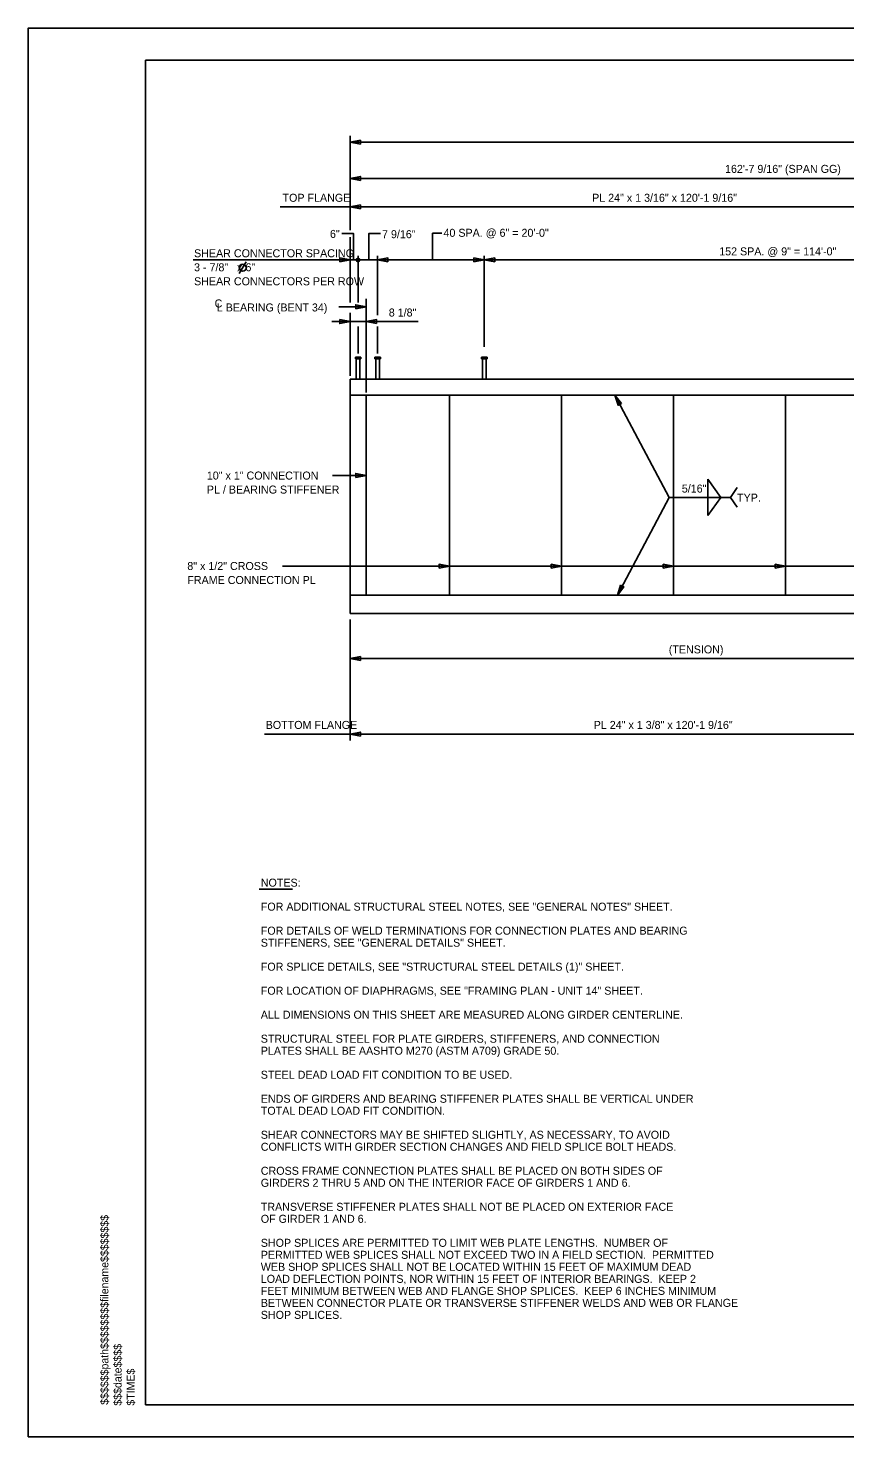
# Model space of a CAD drawing. Extents: x -305 to -161, y -187 to -99.
# Drawn here: x -305.2 to -254.1, y -187.5 to -99.5 of the extents above; entities that cross this region are included whole.
import ezdxf

# ---------------------------------------------------------------- set-up
doc = ezdxf.new("R2010")
doc.units = 0
for name, color, linetype in [('BR_AUTO DIMENSION', 7, 'Continuous'), ('BR_BORDER LINES', 7, 'Continuous'), ('BR_CENTER LINES', 7, 'Continuous'), ('BR_STRUCTURAL STEEL', 7, 'Continuous'), ('BR_TEXT', 7, 'Continuous'), ('Default', 7, 'Continuous'), ('Level 31', 7, 'Continuous'), ('RD_SHT_ID', 7, 'Continuous')]:
    doc.layers.add(name, color=color, linetype=linetype)

msp = doc.modelspace()

# ---------------------------------------------------------------- linework, layer by layer
at = {"layer": 'BR_AUTO DIMENSION'}
for p, q in [((-285.058, -112.102), (-285.058, -106.206)), ((-285.058, -106.618), (-176.638, -106.618)), ((-285.058, -108.876), (-230.848, -108.876)), ((-285.058, -110.653), (-289.428, -110.653)), ((-245.014, -110.653), (-285.055, -110.653)), ((-285.058, -116.618), (-285.058, -112.544)), ((-279.913, -113.971), (-279.913, -112.302)), ((-279.913, -112.302), (-279.327, -112.302)), ((-285.058, -113.971), (-294.871, -113.971)), ((-283.058, -113.971), (-285.058, -113.971)), ((-284.558, -116.618), (-284.558, -113.71)), ((-283.338, -117.422), (-283.338, -113.71)), ((-279.742, -113.971), (-283.055, -113.971)), ((-178.638, -113.971), (-279.742, -113.971)), ((-276.671, -119.402), (-276.671, -113.71)), ((-284.055, -116.897), (-285.757, -116.897)), ((-286.192, -117.821), (-280.799, -117.821)), ((-285.058, -121.218), (-285.058, -117.264)), ((-284.558, -119.81), (-284.558, -118.131)), ((-283.338, -119.81), (-283.338, -118.131)), ((-265.114, -128.801), (-268.502, -122.412)), ((-284.055, -127.431), (-286.165, -127.431)), ((-262.698, -127.667), (-262.698, -129.935)), ((-262.698, -127.667), (-261.892, -128.801)), ((-261.289, -128.801), (-260.856, -128.194)), ((-265.114, -128.801), (-268.355, -134.912)), ((-265.114, -128.801), (-261.289, -128.801)), ((-262.698, -129.935), (-261.892, -128.801)), ((-261.289, -128.801), (-260.856, -129.408)), ((-182.854, -133.101), (-289.275, -133.101)), ((-285.058, -136.437), (-285.058, -143.986)), ((-241.848, -138.867), (-285.058, -138.867)), ((-285.055, -143.585), (-290.402, -143.585)), ((-285.055, -143.585), (-245.014, -143.585)), ((-290.729, -153.28), (-288.653, -153.28))]:
    msp.add_line(p, q, dxfattribs=at)
for points in [[(-284.408, -106.743), (-285.058, -106.618), (-284.408, -106.493)], [(-284.408, -109.001), (-285.058, -108.876), (-284.408, -108.751)], [(-284.408, -110.778), (-285.058, -110.653), (-284.408, -110.528)], [(-285.708, -114.096), (-285.058, -113.971), (-285.708, -113.846)], [(-282.688, -114.096), (-283.338, -113.971), (-282.688, -113.846)], [(-277.321, -114.096), (-276.671, -113.971), (-277.321, -113.846)], [(-276.021, -114.096), (-276.671, -113.971), (-276.021, -113.846)], [(-284.705, -117.022), (-284.055, -116.897), (-284.705, -116.772)], [(-285.708, -117.696), (-285.058, -117.821), (-285.708, -117.946)], [(-283.405, -117.946), (-284.055, -117.821), (-283.405, -117.696)], [(-268.087, -122.928), (-268.502, -122.412), (-268.308, -123.045)], [(-284.705, -127.556), (-284.055, -127.431), (-284.705, -127.306)], [(-279.49, -133.226), (-278.84, -133.101), (-279.49, -132.976)], [(-272.49, -133.226), (-271.84, -133.101), (-272.49, -132.976)], [(-265.49, -133.226), (-264.84, -133.101), (-265.49, -132.976)], [(-258.49, -133.226), (-257.84, -133.101), (-258.49, -132.976)], [(-268.161, -134.28), (-268.355, -134.912), (-267.94, -134.397)], [(-284.408, -138.992), (-285.058, -138.867), (-284.408, -138.742)], [(-284.408, -143.71), (-285.058, -143.585), (-284.408, -143.46)]]:
    msp.add_lwpolyline(points, close=True, dxfattribs=at)
for points in [[(-284.843, -113.971), (-284.843, -112.325), (-285.583, -112.325)], [(-283.895, -113.971), (-283.895, -112.325), (-283.155, -112.325)]]:
    msp.add_lwpolyline(points, dxfattribs=at)
msp.add_circle((-284.558, -113.971), 0.111, dxfattribs=at)
at = {"layer": 'BR_BORDER LINES'}
for p, q in [((-163.178, -101.489), (-297.843, -101.489)), ((-297.843, -185.489), (-297.843, -101.489)), ((-297.843, -185.489), (-163.178, -185.489))]:
    msp.add_line(p, q, dxfattribs=at)
at = {"layer": 'BR_CENTER LINES'}
msp.add_line((-284.055, -116.402), (-284.055, -122.256), dxfattribs=at)
at = {"layer": 'BR_STRUCTURAL STEEL'}
for p, q in [((-285.058, -121.423), (-245.014, -121.423)), ((-285.058, -121.423), (-285.058, -122.412)), ((-285.058, -122.412), (-176.638, -122.412)), ((-285.058, -122.412), (-285.058, -134.912)), ((-284.055, -122.412), (-284.055, -134.912)), ((-278.84, -122.412), (-278.84, -134.912)), ((-271.84, -122.412), (-271.84, -134.912)), ((-264.84, -122.412), (-264.84, -134.912)), ((-257.84, -122.412), (-257.84, -134.912)), ((-285.058, -134.912), (-176.638, -134.912)), ((-285.058, -134.912), (-285.058, -136.058)), ((-285.058, -136.058), (-245.014, -136.058))]:
    msp.add_line(p, q, dxfattribs=at)
at = {"layer": 'BR_TEXT'}
msp.add_line((-291.979, -114.817), (-291.559, -114.089), dxfattribs=at)
msp.add_circle((-291.769, -114.453), 0.22, dxfattribs=at)
at = {"layer": 'Default'}
for p, q in [((-284.729, -120.048), (-284.729, -120.142)), ((-284.729, -120.048), (-284.386, -120.048)), ((-284.729, -120.142), (-284.386, -120.142)), ((-284.667, -120.142), (-284.667, -121.423)), ((-284.448, -120.142), (-284.448, -121.423)), ((-284.386, -120.048), (-284.386, -120.142)), ((-283.509, -120.048), (-283.509, -120.142)), ((-283.509, -120.048), (-283.166, -120.048)), ((-283.509, -120.142), (-283.166, -120.142)), ((-283.447, -120.142), (-283.447, -121.423)), ((-283.228, -120.142), (-283.228, -121.423)), ((-283.166, -120.048), (-283.166, -120.142)), ((-276.843, -120.048), (-276.843, -120.142)), ((-276.843, -120.048), (-276.499, -120.048)), ((-276.843, -120.142), (-276.499, -120.142)), ((-276.78, -120.142), (-276.78, -121.423)), ((-276.562, -120.142), (-276.562, -121.423)), ((-276.499, -120.048), (-276.499, -120.142))]:
    msp.add_line(p, q, dxfattribs=at)
at = {"layer": 'Level 31'}
msp.add_lwpolyline([(-305.176, -187.489), (-161.176, -187.489), (-161.176, -99.489), (-305.176, -99.489)], close=True, dxfattribs=at)

# ---------------------------------------------------------------- texts
at = {"layer": 'BR_AUTO DIMENSION'}
for s, p in [('162\'-7 9/16" (SPAN GG)', (-261.625, -108.53)), ('TOP FLANGE', (-289.279, -110.334)), ('PL 24" x 1 3/16" x 120\'-1 9/16"', (-269.932, -110.334)), ('6"', (-286.315, -112.593)), ('7 9/16"', (-283.06, -112.609)), ('40 SPA. @ 6" = 20\'-0"', (-279.219, -112.522)), ('152 SPA. @ 9" = 114\'-0"', (-261.989, -113.683)), ('8 1/8"', (-282.639, -117.502)), ('5/16"', (-264.326, -128.501)), ('TYP.', (-260.873, -129.067)), ('(TENSION)', (-265.139, -138.548)), ('BOTTOM FLANGE', (-290.331, -143.266)), ('PL 24" x 1 3/8" x 120\'-1 9/16"', (-269.831, -143.266)), ('NOTES:', (-290.637, -153.119)), ('FOR ADDITIONAL STRUCTURAL STEEL NOTES, SEE "GENERAL NOTES" SHEET.', (-290.637, -154.619)), ('FOR DETAILS OF WELD TERMINATIONS FOR CONNECTION PLATES AND BEARING ', (-290.637, -156.119)), ('STIFFENERS, SEE "GENERAL DETAILS" SHEET.', (-290.637, -156.869)), ('FOR SPLICE DETAILS, SEE "STRUCTURAL STEEL DETAILS (1)" SHEET.', (-290.637, -158.369)), ('FOR LOCATION OF DIAPHRAGMS, SEE "FRAMING PLAN - UNIT 14" SHEET.', (-290.637, -159.869)), ('ALL DIMENSIONS ON THIS SHEET ARE MEASURED ALONG GIRDER CENTERLINE.', (-290.637, -161.369)), ('STRUCTURAL STEEL FOR PLATE GIRDERS, STIFFENERS, AND CONNECTION ', (-290.637, -162.869)), ('PLATES SHALL BE AASHTO M270 (ASTM A709) GRADE 50.', (-290.637, -163.619)), ('STEEL DEAD LOAD FIT CONDITION TO BE USED.', (-290.637, -165.119)), ('ENDS OF GIRDERS AND BEARING STIFFENER PLATES SHALL BE VERTICAL UNDER', (-290.637, -166.619)), ('TOTAL DEAD LOAD FIT CONDITION.', (-290.637, -167.369)), ('SHEAR CONNECTORS MAY BE SHIFTED SLIGHTLY, AS NECESSARY, TO AVOID ', (-290.637, -168.869)), ('CONFLICTS WITH GIRDER SECTION CHANGES AND FIELD SPLICE BOLT HEADS.', (-290.637, -169.619)), ('CROSS FRAME CONNECTION PLATES SHALL BE PLACED ON BOTH SIDES OF ', (-290.637, -171.119)), ('GIRDERS 2 THRU 5 AND ON THE INTERIOR FACE OF GIRDERS 1 AND 6.', (-290.637, -171.869)), ('TRANSVERSE STIFFENER PLATES SHALL NOT BE PLACED ON EXTERIOR FACE ', (-290.637, -173.369)), ('OF GIRDER 1 AND 6.', (-290.637, -174.119)), ('SHOP SPLICES ARE PERMITTED TO LIMIT WEB PLATE LENGTHS.  NUMBER OF ', (-290.637, -175.619)), ('PERMITTED WEB SPLICES SHALL NOT EXCEED TWO IN A FIELD SECTION.  PERMITTED', (-290.637, -176.369)), ('WEB SHOP SPLICES SHALL NOT BE LOCATED WITHIN 15 FEET OF MAXIMUM DEAD', (-290.637, -177.119)), ('LOAD DEFLECTION POINTS, NOR WITHIN 15 FEET OF INTERIOR BEARINGS.  KEEP 2', (-290.637, -177.869)), ('FEET MINIMUM BETWEEN WEB AND FLANGE SHOP SPLICES.  KEEP 6 INCHES MINIMUM ', (-290.637, -178.619)), ('BETWEEN CONNECTOR PLATE OR TRANSVERSE STIFFENER WELDS AND WEB OR FLANGE', (-290.637, -179.369)), ('SHOP SPLICES.', (-290.637, -180.119))]:
    msp.add_text(s, height=0.5, rotation=360, dxfattribs=at).set_placement(p)
at = {"layer": 'BR_TEXT'}
for s, p in [('SHEAR CONNECTOR SPACING', (-294.808, -113.801)), ('3 - 7/8"   x 6" ', (-294.808, -114.676)), ('SHEAR CONNECTORS PER ROW', (-294.808, -115.551)), ('C', (-293.523, -116.936)), ('L BEARING (BENT 34)', (-293.387, -117.186)), ('10" x 1" CONNECTION ', (-294.01, -127.688)), ('PL / BEARING STIFFENER', (-294.01, -128.563)), ('8" x 1/2" CROSS ', (-295.229, -133.338)), ('FRAME CONNECTION PL', (-295.229, -134.213))]:
    msp.add_text(s, height=0.5, rotation=360, dxfattribs=at).set_placement(p)
at = {"layer": 'RD_SHT_ID'}
for s, height, p in [('$$$$$$path$$$$$$$$filename$$$$$$$$', 0.49387, (-300.161, -185.489)), ('$$$date$$$$', 0.49387, (-299.338, -185.542)), ('$TIME$', 0.4939, (-298.52, -185.542))]:
    msp.add_text(s, height=height, rotation=90, dxfattribs=at).set_placement(p)

doc.saveas('drawing.dxf')
